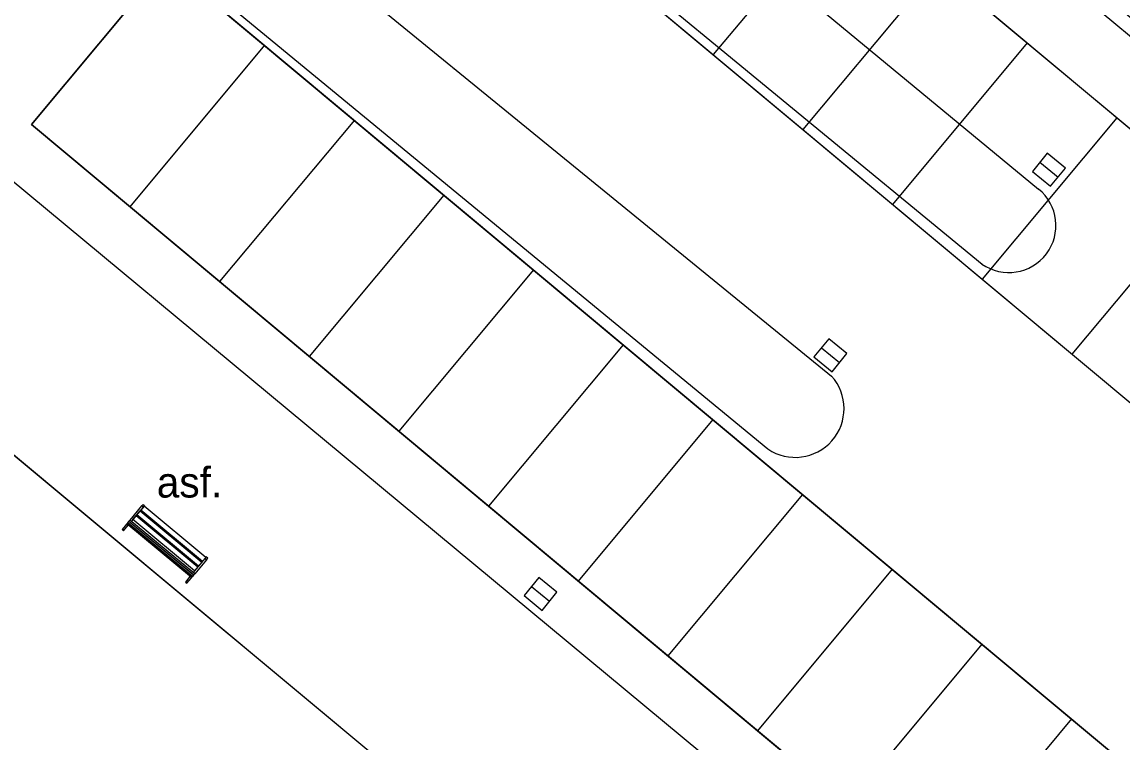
# Model space of a CAD drawing. Extents: x -438303 to -437792, y -1133191 to -1132731.
# Drawn here: x -438101.3 to -438077.75, y -1132997.67 to -1132982.24 of the extents above; entities that cross this region are included whole.
import ezdxf

# ---------------------------------------------------------------- set-up
doc = ezdxf.new("R2010")
doc.units = 0
for name, color, linetype in [('Default', 7, 'Continuous'), ('MOBILIÁŘ', 7, 'Continuous'), ('Vrstva 1', 7, 'Continuous'), ('Vrstva 10', 7, 'Continuous'), ('Vrstva 27', 7, 'Continuous'), ('Vrstva 40', 7, 'Continuous'), ('Vrstva 5', 7, 'Continuous'), ('Vrstva 50', 7, 'Continuous'), ('Vrstva 55', 7, 'Continuous')]:
    doc.layers.add(name, color=color, linetype=linetype)

# ---------------------------------------------------------------- blocks, each defined once
blk = doc.blocks.new('A$C6FF56919')
at = {"layer": 'Vrstva 1'}
for p, q in [((-18000, 5423), (-18000, 5482)), ((-18000, 5482), (-17605, 5482)), ((-18000, 5423), (0, 5423)), ((-18000, 5108), (-18000, 5423)), ((-18000, 5108), (0, 5108)), ((-18000, 4771), (-18000, 5108)), ((-18000, 4771), (0, 4771)), ((-18000, 4707), (-18000, 4771)), ((-17605, 5482), (-17605, 7031)), ((-17605, 5423), (-17605, 5482)), ((-401, 7031), (-401, 5482)), ((0, 7031), (-401, 7031)), ((-401, 5482), (0, 5482)), ((-401, 5423), (-401, 5482)), ((0, 5482), (0, 7031)), ((0, 5423), (0, 5482)), ((0, 5423), (0, 5108)), ((0, 5108), (0, 4771)), ((0, 4771), (0, 4707)), ((0, 4707), (-18000, 4707)), ((-18000, 4707), (-18000, 4365)), ((-18000, 459), (-18000, 4365)), ((-18000, 4365), (0, 4365)), ((-17605, 459), (-17605, 4365)), ((-17605, 3703), (-17594, 3703)), ((-17605, 2907), (-17594, 2907)), ((-17605, 2901), (-17594, 2901)), ((-17605, 2410), (-17594, 2410)), ((-17594, 2805), (-17594, 3895)), ((-411, 2805), (-17594, 2805)), ((-17594, 2805), (-17594, 2762)), ((-17594, 2762), (-411, 2762)), ((-17594, 2575), (-411, 2575)), ((-17594, 1475), (-17594, 2575)), ((-9200, 2575), (-9200, 2762)), ((-8799, 2575), (-8799, 2762)), ((-401, 3703), (-411, 3703)), ((-401, 2907), (-411, 2907)), ((-401, 2901), (-411, 2901)), ((-411, 2762), (-411, 2805)), ((-411, 2575), (-411, 1475)), ((-401, 2410), (-411, 2410)), ((-401, 459), (-401, 4365)), ((0, 4365), (0, 4707)), ((0, 459), (0, 4365)), ((-18000, 459), (-18000, 0)), ((-17605, 459), (-18000, 459)), ((-18000, 0), (-17605, 0)), ((-17605, 1608), (-17594, 1608)), ((-17605, 1608), (-17594, 1608)), ((-17605, 1106), (-17594, 1106)), ((-17605, 1106), (-17594, 1106)), ((-17605, 0), (-17605, 459)), ((-17605, 305), (-17594, 305)), ((-17594, 1459), (-17594, 1475)), ((-17594, 1475), (-411, 1475)), ((-411, 1459), (-17594, 1459)), ((-17594, 1245), (-17594, 1256)), ((-17594, 1256), (-411, 1256)), ((-17594, 1245), (-17594, 144)), ((-411, 1245), (-17594, 1245)), ((-17594, 144), (-411, 144)), ((-9200, 1256), (-9200, 1459)), ((-8800, 1256), (-8800, 1459)), ((-401, 1608), (-411, 1608)), ((-401, 1608), (-411, 1608)), ((-411, 1475), (-411, 1459)), ((-411, 1256), (-411, 1245)), ((-411, 144), (-411, 1245)), ((-401, 1106), (-411, 1106)), ((-401, 1106), (-411, 1106)), ((-401, 305), (-411, 305)), ((-401, 459), (0, 459)), ((-401, 0), (-401, 459)), ((0, 0), (-401, 0)), ((0, 459), (0, 0))]:
    blk.add_line(p, q, dxfattribs=at)
for points in [[(-17605, 7031), (-18000, 7031), (-18000, 5482)], [(-17594, 3895), (-411, 3895), (-411, 2805)]]:
    blk.add_lwpolyline(points, dxfattribs=at)
blk = doc.blocks.new('A$C73EC33FB')
at = {"layer": 'Default'}
for points in [[(-39000, 25012), (0, 25012), (0, 0), (-39000, 0)], [(-32310, 18759), (-31900, 18759), (-31900, 9105), (-32310, 9105)], [(-26014, 18759), (-25605, 18759), (-25605, 9105), (-26014, 9105)], [(-19705, 18759), (-19295, 18759), (-19295, 9105), (-19705, 9105)], [(-13409, 18759), (-13000, 18759), (-13000, 9105), (-13409, 9105)], [(-7100, 18759), (-6690, 18759), (-6690, 9105), (-7100, 9105)]]:
    blk.add_lwpolyline(points, close=True, dxfattribs=at)

msp = doc.modelspace()

# ---------------------------------------------------------------- linework, layer by layer
at = {"layer": 'Vrstva 1'}
for p, q in [((-438091.487, -1132972.918), (-438066.153, -1132994.064)), ((-438091.487, -1132972.918), (-438066.153, -1132994.064)), ((-438094.371, -1132976.373), (-438069.036, -1132997.519)), ((-438094.371, -1132976.373), (-438069.036, -1132997.519)), ((-438083.618, -1132979.486), (-438086.502, -1132982.941)), ((-438083.618, -1132979.486), (-438086.502, -1132982.941)), ((-438098.216, -1132980.979), (-438101.099, -1132984.434)), ((-438098.216, -1132980.979), (-438101.099, -1132984.434)), ((-438098.216, -1132980.979), (-438072.881, -1133002.125)), ((-438098.216, -1132980.979), (-438072.881, -1133002.125)), ((-438081.699, -1132981.088), (-438084.583, -1132984.543)), ((-438081.699, -1132981.088), (-438084.583, -1132984.543)), ((-438096.105, -1132982.741), (-438098.988, -1132986.196)), ((-438096.105, -1132982.741), (-438098.988, -1132986.196)), ((-438079.78, -1132982.69), (-438082.663, -1132986.145)), ((-438079.78, -1132982.69), (-438082.663, -1132986.145)), ((-438092.066, -1132983.252), (-438092.066, -1132983.252)), ((-438094.185, -1132984.343), (-438097.069, -1132987.798)), ((-438094.185, -1132984.343), (-438097.069, -1132987.798)), ((-438077.86, -1132984.292), (-438080.744, -1132987.747)), ((-438077.86, -1132984.292), (-438080.744, -1132987.747)), ((-438101.099, -1132984.434), (-438075.765, -1133005.58)), ((-438101.099, -1132984.434), (-438075.765, -1133005.58)), ((-438093.568, -1132984.597), (-438093.568, -1132984.597)), ((-438079.315, -1132985.403), (-438079.315, -1132985.403)), ((-438092.266, -1132985.945), (-438095.15, -1132989.4)), ((-438092.266, -1132985.945), (-438095.15, -1132989.4)), ((-438079.536, -1132985.818), (-438079.536, -1132985.818)), ((-438075.941, -1132985.894), (-438078.825, -1132989.349)), ((-438075.941, -1132985.894), (-438078.825, -1132989.349)), ((-438079.352, -1132987.179), (-438079.352, -1132987.179)), ((-438080.748, -1132987.422), (-438080.748, -1132987.422)), ((-438090.347, -1132987.547), (-438093.23, -1132991.002)), ((-438090.347, -1132987.547), (-438093.23, -1132991.002)), ((-438088.427, -1132989.149), (-438091.311, -1132992.604)), ((-438088.427, -1132989.149), (-438091.311, -1132992.604)), ((-438083.993, -1132989.376), (-438083.993, -1132989.376)), ((-438083.967, -1132989.82), (-438083.967, -1132989.82)), ((-438086.508, -1132990.751), (-438089.392, -1132994.206)), ((-438086.508, -1132990.751), (-438089.392, -1132994.206)), ((-438085.333, -1132991.379), (-438085.333, -1132991.379)), ((-438084.589, -1132992.353), (-438087.472, -1132995.808)), ((-438084.589, -1132992.353), (-438087.472, -1132995.808)), ((-438082.67, -1132993.955), (-438085.553, -1132997.41)), ((-438082.67, -1132993.955), (-438085.553, -1132997.41)), ((-438090.828, -1132994.505), (-438090.828, -1132994.505)), ((-438090.199, -1132994.482), (-438090.199, -1132994.482)), ((-438080.75, -1132995.557), (-438083.634, -1132999.012)), ((-438080.75, -1132995.557), (-438083.634, -1132999.012)), ((-438078.831, -1132997.159), (-438081.715, -1133000.614)), ((-438078.831, -1132997.159), (-438081.715, -1133000.614))]:
    msp.add_line(p, q, dxfattribs=at)
at = {"layer": 'Vrstva 10'}
msp.add_lwpolyline([(-438136.822, -1132975.739), (-438130.734, -1132968.465), (-438110.798, -1132985.034), (-438109.098, -1132982.99), (-438101.579, -1132989.251), (-438102.65, -1132990.536), (-438091.05, -1133000.193), (-438097.754, -1133008.211)], close=True, dxfattribs=at)
msp.add_lwpolyline([(-438136.822, -1132975.739), (-438130.734, -1132968.465), (-438110.798, -1132985.034), (-438109.098, -1132982.99), (-438101.579, -1132989.251), (-438102.65, -1132990.536), (-438091.05, -1133000.193), (-438097.754, -1133008.211)], close=True, dxfattribs=at)
for points in [[(-438092.668, -1132970.017), (-438076.291, -1132983.61)], [(-438095.633, -1132972.528), (-438079.536, -1132985.818)], [(-438096.986, -1132974.066), (-438080.748, -1132987.422)], [(-438100.236, -1132976.563), (-438083.967, -1132989.82)], [(-438101.554, -1132978.022), (-438085.333, -1132991.379)], [(-438106.353, -1132981.61), (-438090.828, -1132994.505), (-438086.747, -1132997.891), (-438085.017, -1132998.807), (-438079.71, -1133001.136), (-438076.129, -1133002.536)]]:
    msp.add_lwpolyline(points, dxfattribs=at)
for centre, radius, start, end in [((-438080.172, -1132986.597), 1.006, 235.0406, 50.7779), ((-438084.747, -1132990.515), 1.045, 235.8479, 41.713)]:
    msp.add_arc(centre, radius, start, end, dxfattribs=at)
at = {"layer": 'Vrstva 27'}
for p, q in [((-438079.509, -1132985.245), (-438079.121, -1132985.561)), ((-438084.187, -1132989.218), (-438083.798, -1132989.533)), ((-438090.394, -1132994.324), (-438090.005, -1132994.639))]:
    msp.add_line(p, q, dxfattribs=at)
for points in [[(-438079.667, -1132985.439), (-438079.279, -1132985.755), (-438078.963, -1132985.367), (-438079.351, -1132985.051)], [(-438084.345, -1132989.411), (-438083.957, -1132989.727), (-438083.641, -1132989.34), (-438084.028, -1132989.024)], [(-438090.551, -1132994.517), (-438090.164, -1132994.834), (-438089.847, -1132994.446), (-438090.235, -1132994.13)]]:
    msp.add_lwpolyline(points, close=True, dxfattribs=at)
at = {"layer": 'Vrstva 5'}
msp.add_line((-438091.05, -1133000.193), (-438102.65, -1132990.536), dxfattribs=at)
at = {"layer": 'Vrstva 50'}
for points in [[(-438091.487, -1132972.918), (-438066.145, -1132994.07), (-438069.029, -1132997.525), (-438094.371, -1132976.373)], [(-438091.487, -1132972.918), (-438066.145, -1132994.07), (-438069.029, -1132997.525), (-438094.371, -1132976.373)], [(-438098.216, -1132980.979), (-438072.883, -1133002.124), (-438075.766, -1133005.578), (-438101.099, -1132984.434)], [(-438098.216, -1132980.979), (-438072.883, -1133002.124), (-438075.766, -1133005.578), (-438101.099, -1132984.434)]]:
    msp.add_lwpolyline(points, close=True, dxfattribs=at)

# ---------------------------------------------------------------- block references
at = {"layer": 'MOBILIÁŘ', "xscale": 0.00010000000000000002, "yscale": 0.00010000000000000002}
for name, p, rotation in [('A$C73EC33FB', (-438076.066, -1132983.402), -39.862018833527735), ('A$C73EC33FB', (-438076.066, -1132983.402), -39.862018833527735), ('A$C6FF56919', (-438098.709, -1132992.565), 140.3308551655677)]:
    msp.add_blockref(name, p, dxfattribs=dict(at, rotation=rotation))

# ---------------------------------------------------------------- texts
at = {"layer": 'Vrstva 40'}
msp.add_text('asf.', height=0.65, rotation=0.1042, dxfattribs=at).set_placement((-438098.414, -1132992.42))
at = {"layer": 'Vrstva 55'}
msp.add_text('AUTOBUSOVÉ STANOVIŠTE', height=1.49999, rotation=320.2068, dxfattribs=at).set_placement((-438121.818, -1132983.3))

doc.saveas('drawing.dxf')
